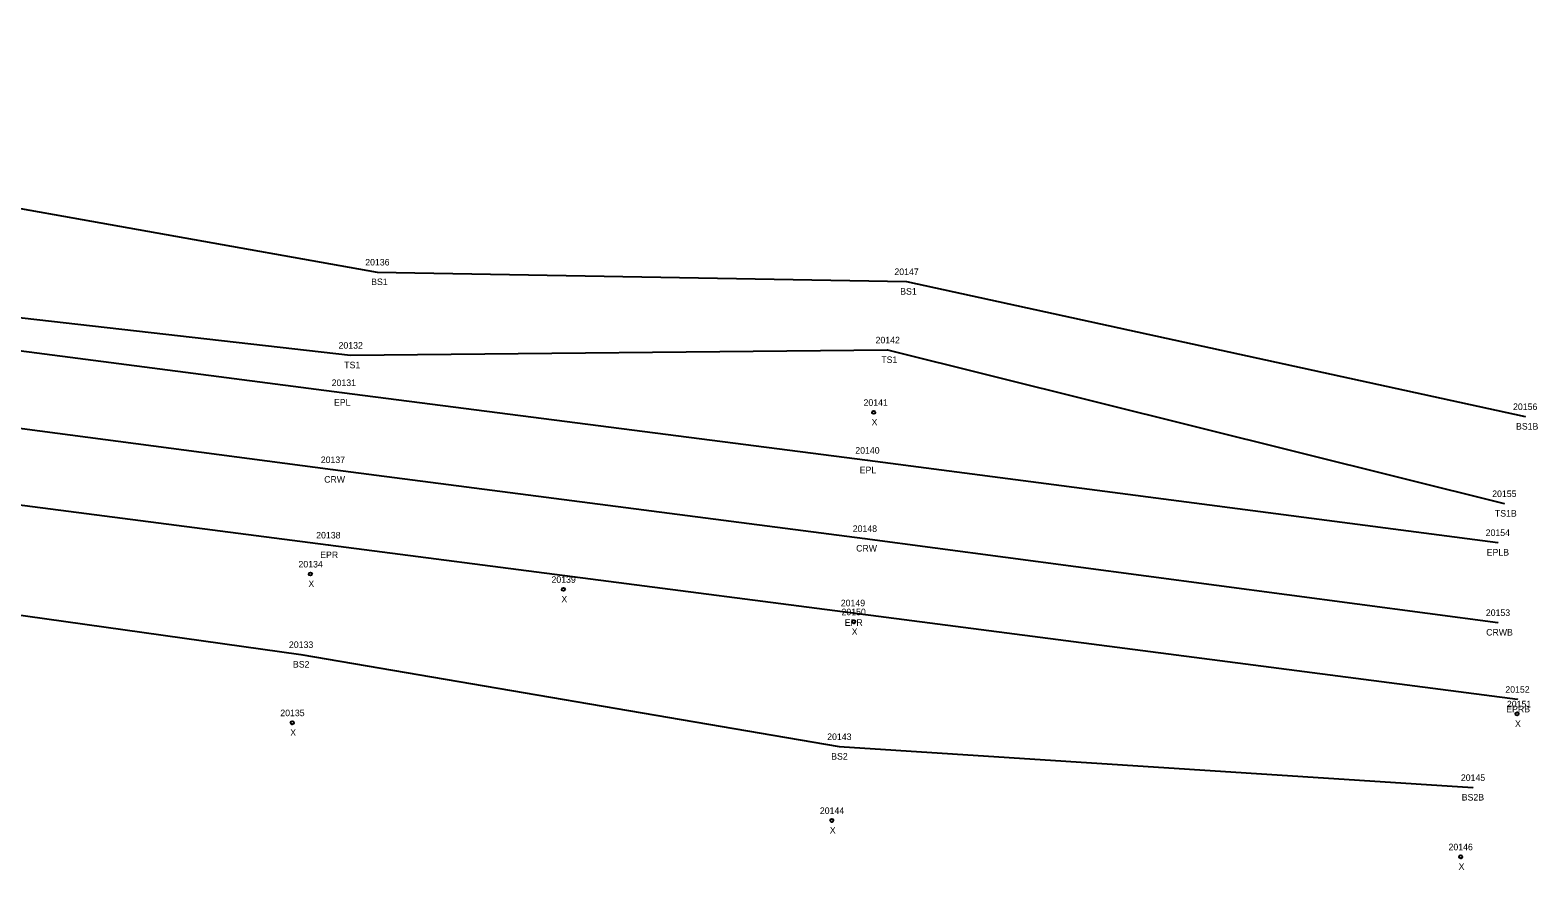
# Model space of a CAD drawing. Extents: x 2080935 to 2082049, y 730754 to 730962.
# Drawn here: x 2081818.5 to 2082049.1, y 730754.4 to 730882.9 of the extents above; entities that cross this region are included whole.
import ezdxf

# ---------------------------------------------------------------- set-up
doc = ezdxf.new("R2010")
doc.units = 0
for name, color, linetype in [('RD_DTM_BkLn1', 7, 'Continuous'), ('RD_DTM_BkLn2', 7, 'Continuous'), ('RD_EX_Road', 7, 'Continuous'), ('RD_EX_Road_txCode', 7, 'Continuous'), ('RD_Sketch8', 7, 'Continuous'), ('RD_SMD_Locator', 7, 'Continuous'), ('RD_SMD_Misc', 7, 'Continuous')]:
    doc.layers.add(name, color=color, linetype=linetype)

msp = doc.modelspace()

# ---------------------------------------------------------------- linework, layer by layer
at = {"layer": 'RD_DTM_BkLn1'}
msp.add_lwpolyline([(2081567.45, 730853.84), (2081663.53, 730841.7), (2081762.3, 730829.16), (2081864.76, 730815.62), (2081946.16, 730805.08), (2082043.01, 730792.22)], dxfattribs=at)
at = {"layer": 'RD_DTM_BkLn2'}
for points in [[(2081573.98, 730882.88), (2081669.72, 730874.22), (2081770.38, 730863.88), (2081871.58, 730845.86), (2081952.53, 730844.4), (2082047.2, 730823.74)], [(2081567.86, 730866.16), (2081571.2, 730868.83), (2081575.19, 730876.18), (2081667.17, 730866.99), (2081764.74, 730844.81), (2081867.48, 730833.13), (2081949.65, 730833.94), (2082043.99, 730810.42)], [(2081562.68, 730817.88), (2081660.31, 730811.19), (2081763.58, 730800.86), (2081859.9, 730787.32), (2081942.25, 730773.23), (2082039.2, 730766.97)]]:
    msp.add_lwpolyline(points, dxfattribs=at)
at = {"layer": 'RD_EX_Road'}
for points in [[(2081567.45, 730853.84), (2081569.41, 730865.32), (2081665.09, 730853.16), (2081763.75, 730840.72), (2081866.15, 730827.41), (2081946.59, 730817.06), (2082042.99, 730804.46)], [(2081567.45, 730853.84), (2081564.7, 730842.25), (2081662.62, 730830.19), (2081761.36, 730817.44), (2081864.07, 730804.08), (2081944.33, 730793.7), (2082046, 730780.47)]]:
    msp.add_lwpolyline(points, dxfattribs=at)
at = {"layer": 'RD_SMD_Locator'}
for centre, radius in [((2081871.58, 730845.86), 0.001), ((2081952.53, 730844.4), 0.001), ((2081867.48, 730833.13), 0.001), ((2081949.65, 730833.94), 0.001), ((2081866.15, 730827.41), 0.001), ((2081947.52, 730824.38), 0.25), ((2082047.2, 730823.74), 0.001), ((2081946.59, 730817.06), 0.001), ((2081864.76, 730815.62), 0.001), ((2082043.99, 730810.42), 0.001), ((2081946.16, 730805.08), 0.001), ((2081864.07, 730804.08), 0.001), ((2082042.99, 730804.46), 0.001), ((2081861.35, 730799.64), 0.25), ((2081900.06, 730797.29), 0.25), ((2081944.33, 730793.7), 0.001), ((2081944.48, 730792.33), 0.25), ((2082043.01, 730792.22), 0.001), ((2081859.9, 730787.32), 0.001), ((2082046, 730780.47), 0.001), ((2082045.95, 730778.23), 0.25), ((2081858.57, 730776.88), 0.25), ((2081942.25, 730773.23), 0.001), ((2082039.2, 730766.97), 0.001), ((2081941.12, 730761.92), 0.25), ((2082037.33, 730756.36), 0.25)]:
    msp.add_circle(centre, radius, dxfattribs=at)

# ---------------------------------------------------------------- texts
at = {"layer": 'RD_EX_Road_txCode'}
for s, p in [('20131', (2081864.6, 730828.41)), ('EPL', (2081864.95, 730825.41)), ('20140', (2081944.71, 730818.06)), ('EPL', (2081945.38, 730815.06)), ('20138', (2081862.23, 730805.08)), ('20154', (2082041.15, 730805.46)), ('EPR', (2081862.84, 730802.08)), ('EPLB', (2082041.31, 730802.46)), ('20149', (2081942.49, 730794.7)), ('EPR', (2081943.1, 730791.7)), ('20152', (2082044.16, 730781.47)), ('EPRB', (2082044.3, 730778.47))]:
    msp.add_text(s, height=1, dxfattribs=at).set_placement(p)
at = {"layer": 'RD_Sketch8'}
for s, p in [('20141', (2081945.97, 730825.38)), ('X', (2081947.2, 730822.38)), ('20134', (2081859.52, 730800.64)), ('X', (2081861.04, 730797.64)), ('20139', (2081898.23, 730798.29)), ('X', (2081899.75, 730795.29)), ('20150', (2081942.6, 730793.33)), ('X', (2081944.16, 730790.33)), ('20151', (2082044.4, 730779.23)), ('20135', (2081856.74, 730777.88)), ('X', (2081858.26, 730774.88)), ('X', (2082045.64, 730776.23)), ('20144', (2081939.29, 730762.92)), ('X', (2081940.81, 730759.92)), ('20146', (2082035.47, 730757.36)), ('X', (2082037.01, 730754.36))]:
    msp.add_text(s, height=1, dxfattribs=at).set_placement(p)
at = {"layer": 'RD_SMD_Misc'}
for s, p in [('20136', (2081869.73, 730846.86)), ('BS1', (2081870.64, 730843.86)), ('20147', (2081950.69, 730845.4)), ('BS1', (2081951.58, 730842.4)), ('20132', (2081865.65, 730834.13)), ('20142', (2081947.81, 730834.94)), ('TS1', (2081948.69, 730831.94)), ('TS1', (2081866.52, 730831.13)), ('20156', (2082045.34, 730824.74)), ('BS1B', (2082045.79, 730821.74)), ('20137', (2081862.93, 730816.62)), ('CRW', (2081863.45, 730813.62)), ('20155', (2082042.15, 730811.42)), ('TS1B', (2082042.56, 730808.42)), ('20148', (2081944.32, 730806.08)), ('CRW', (2081944.84, 730803.08)), ('20153', (2082041.18, 730793.22)), ('CRWB', (2082041.23, 730790.22)), ('20133', (2081858.06, 730788.32)), ('BS2', (2081858.67, 730785.32)), ('20143', (2081940.41, 730774.23)), ('BS2', (2081941.02, 730771.23)), ('20145', (2082037.36, 730767.97)), ('BS2B', (2082037.49, 730764.97))]:
    msp.add_text(s, height=1, dxfattribs=at).set_placement(p)

doc.saveas('drawing.dxf')
